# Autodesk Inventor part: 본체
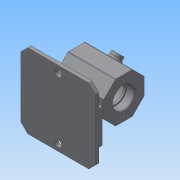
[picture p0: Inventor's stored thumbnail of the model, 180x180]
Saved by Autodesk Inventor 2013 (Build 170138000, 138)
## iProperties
Created: 2018-06
Part Number: 본체
Material: 일반
Document SubType Name: Modeling
Designer: Administrator
Density: 1 g/cm^3
Author: Administrator
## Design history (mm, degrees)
sketch "스케치1"
  geometry: L1 (-30, -12.426)-(-30, 12.426); L2 (-30, 12.426)-(-12.426, 30); L3 (-12.426, 30)-(12.426, 30); L4 (12.426, 30)-(30, 12.426); L5 (30, 12.426)-(30, -12.426); L6 (30, -12.426)-(12.426, -30); L7 (12.426, -30)-(-12.426, -30); L8 (-12.426, -30)-(-30, -12.426); 3 further points
  constraints: 16 end point, 1 coincident, 1 midpoint, 1 vertical alignment, 17 other
  dimensions: "d0" = 30 distance from line of L5 point (0, 0)
extrude "돌출1" new body sketch "스케치1" stored distance "d1" = 70; taper "d2" = 0 deg
node "작업 평면1"
sketch "스케치2"
  geometry: L1 (-55, 55)-(55, 55); L2 (55, 55)-(55, -55); L3 (55, -55)-(-55, -55); L4 (-55, -55)-(-55, 55); L5 (-55, 55)-(55, -55); L6 (55, 55)-(-55, -55); 1 further point
  constraints: 12 end point, 2 midpoint, 2 parallel, 1 horizontal, 1 perpendicular
  dimensions: "d4" = 110 distance of L2.end L3.end; "d6" = 110 distance of L3.end L1.start
extrude "돌출2" join sketch "스케치2" distance "d7" = 5; taper "d8" = 0 deg
sketch "스케치3"
  geometry: L1 (55, 55)-(-55, 55) reference; L2 (-55, 55)-(-55, -55) reference; L3 (55, -25)-(-55, -25); L4 (-55, -25)-(-55, 25); L5 (-55, 25)-(55, 25); L6 (55, 25)-(55, -25); L7 (55, -25)-(-55, 25); L8 (-55, -25)-(55, 25); 1 further point
  constraints: 12 end point, 2 midpoint, 2 parallel, 1 horizontal, 1 perpendicular, 1 point on line
  dimensions: "d9" = 30 distance between parallel lines of L1 L5
extrude "돌출3" join sketch "스케치3" distance "d10" = 5; taper "d11" = 0 deg
chamfer "모따기1" distance "d12" = 10; stored, may be unused: second distance "d13" = 2, angle "d14" = 45 deg
sketch "스케치4"
  geometry: L1 (45, 55)-(-45, 55) reference; L2 (-55, 45)-(-55, 25) reference; C1 r 5 at (0, 45); 1 further point
  constraints: 1 centre point
  dimensions: "d15" = 10 diameter of C1; "d17" = 55 distance from line of C1.centre L2; "d18" = 10 distance from line of C1.centre L1
extrude "돌출4" cut sketch "스케치4" distance "d19" = 55 (= d17); taper "d20" = 0 deg
sketch "스케치5"
  geometry: L1 (55, 25)-(-55, 25) reference; L2 (-19, 5)-(19, 5); L3 (19, -5)-(-19, -5); A1 r 5 centre (19, 0) between (19, -5) and (19, 5); A2 r 5 centre (-19, 0) between (-19, 5) and (-19, -5); 2 further points
  constraints: 4 end point, 4 point on circle, 4 tangent, 2 centre point, 2 parallel, 1 horizontal alignment, 1 midpoint, 1 vertical alignment
  dimensions: "d21" = 38 distance of L2.start L2.end; "d23" = 5 radius of A1
extrude "돌출5" join sketch "스케치5" stored distance "d24" = 55 (= d17); taper "d25" = 0 deg
node "작업 평면2"
sketch "스케치6"
  geometry: C1 r 8 at (35, 12.426); 1 further point
  constraints: 1 centre point, 1 coincident
  dimensions: "d27" = 16 diameter of C1
extrude "돌출6" join sketch "스케치6" stored distance "d29" = 55 (= d17); taper "d30" = 0 deg
sketch "스케치7"
  geometry: 3 further points
  constraints: 1 coincident, 1 vertical alignment
  dimensions: "d31" = 23 distance of point (0, 0) point (0, 23)
hole "구멍1" sketch "스케치7" diameter "d32" = 28; stored, may be unused: countersink angle "d36" = 90 deg, drill point angle "d38" = 0 deg; dims "d33" = 6, "d34" = 32, "d35" = 12, "d37" = 15
hole "구멍2" sketch "스케치7" diameter "d39" = 3.242; stored, may be unused: countersink angle "d43" = 90 deg, drill point angle "d45" = 118 deg; dims "d40" = 8, "d41" = 32, "d42" = 12, "d44" = 10
hole "구멍3" diameter "d51" = 50; stored, may be unused: countersink angle "d55" = 90 deg, drill point angle "d57" = 0 deg; dims "d49" = 10, "d50" = 10, "d52" = 8, "d53" = 32, "d54" = 12, "d56" = 40
hole "구멍4" diameter "d60" = 8; stored, may be unused: countersink angle "d64" = 90 deg, drill point angle "d66" = 0 deg; dims "d58" = 10, "d59" = 10, "d61" = 8, "d62" = 32, "d63" = 12, "d65" = 40
sketch "스케치8"
  geometry: L1 (0, 0)-(0, 24.853) reference; L2 (70, 42.426)-(0, 42.426) reference; L3 (0, 24.853)-(0, 42.426) reference; 2 further points
  constraints: 1 other
  dimensions: "d67" = 30 distance from line of point (35, 12.426) L2; "d68" = 35 distance from line of point (35, 12.426) L1
feature "엠보싱1" sketch "스케치8" dims "d0" = 30, "d69" = 0.5, "d70" = 0
fillet "모깎기1" dims "d71" = 1, "d72" = 0.3, "d73" = 3, "d74" = 2
chamfer "모따기2" distance "d75" = 1; stored, may be unused: second distance "d76" = 2, angle "d77" = 45 deg
node "솔리드1"
mirror "대칭1"
pattern_circular "원형 패턴1" dims angle "d47" = 360 deg
mirror "대칭2"
other parameters: "d3" = -62, "d26" = 7
